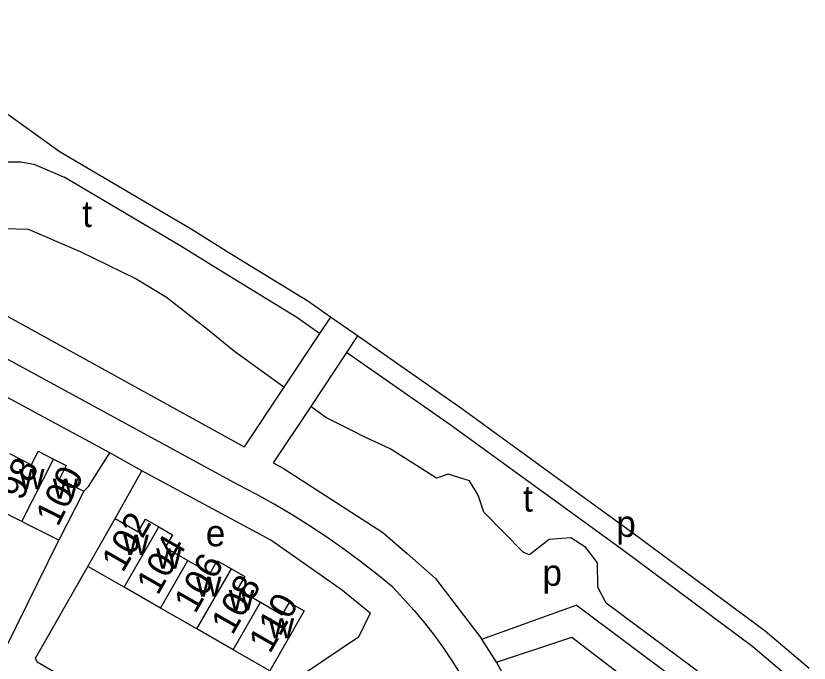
# Model space of a CAD drawing. Extents: x 163012 to 165277, y 382513 to 383987.
# Drawn here: x 164219.5 to 164339.9, y 383557.5 to 383655.8 of the extents above; entities that cross this region are included whole.
import ezdxf

# ---------------------------------------------------------------- set-up
doc = ezdxf.new("R2010")
doc.units = 0
for name, color, linetype in [('BLT_Basislijn', 7, 'Continuous'), ('BLT_Bebouwing', 7, 'Continuous'), ('BLT_Centroide', 7, 'Continuous'), ('BLT_Huisnummer', 7, 'Continuous'), ('BLT_Huisnummer_ tussenligend', 7, 'Continuous'), ('BLT_Onderverdeling_panden', 7, 'Continuous')]:
    doc.layers.add(name, color=color, linetype=linetype)

msp = doc.modelspace()

# ---------------------------------------------------------------- linework, layer by layer
at = {"layer": 'BLT_Basislijn'}
for p, q in [((164253.23, 383584.61), (164174.38, 383627.47)), ((164267.25, 383610.06), (164265.59, 383607.56)), ((164265.59, 383607.56), (164260.18, 383599.42)), ((164271.35, 383607.19), (164269.69, 383604.69)), ((164269.69, 383604.69), (164264.24, 383596.49)), ((164260.18, 383599.42), (164254.16, 383590.37)), ((164264.24, 383596.49), (164258.55, 383587.95)), ((164238.63, 383586.7), (164233.73, 383589.42)), ((164234.57, 383579.46), (164238.63, 383586.7)), ((164292.43, 383557.65), (164290.23, 383561.18))]:
    msp.add_line(p, q, dxfattribs=at)
for points in [[(164260.18, 383599.42), (164252.68, 383604.84), (164248.56, 383608.19), (164242.36, 383613.04), (164237.58, 383615.93), (164229.31, 383619.94), (164221.42, 383623.35), (164217.69, 383623.42), (164211.33, 383622.65), (164207.69, 383623.26), (164204.58, 383624.44), (164202.52, 383625.33), (164199.96, 383627.38), (164196.94, 383630.37), (164195.36, 383632.54), (164193.6, 383635.55), (164192.09, 383638.68), (164189.84, 383644.26), (164189.47, 383645.58), (164189.18, 383647.27), (164189.7, 383651.82), (164189.86, 383654.86), (164189.34, 383655.77)], [(164267.25, 383610.06), (164263.78, 383612.49), (164251.8, 383619.82), (164246.07, 383623.4), (164226.22, 383635.1), (164207.98, 383648.12)], [(164202.53, 383633.42), (164203.91, 383632.72), (164205.4, 383632.16), (164206.96, 383631.77), (164208.58, 383631.56), (164210.22, 383631.54), (164211.84, 383631.7), (164213.41, 383632.05), (164214.91, 383632.57), (164216.32, 383633.23), (164218.17, 383633.61), (164220.24, 383633.61), (164222.21, 383633.24), (164226.8, 383631.28)], [(164179.62, 383631.43), (164254.16, 383590.37)], [(164265.59, 383607.56), (164262.13, 383609.98), (164250.22, 383617.27), (164244.51, 383620.83), (164226.8, 383631.28)], [(164233.73, 383589.42), (164177.23, 383619.95), (164175.65, 383621.7)], [(164271.35, 383607.19), (164267.25, 383610.06)], [(164333.21, 383562.36), (164313.32, 383577.12), (164287.17, 383596.12), (164271.35, 383607.19)], [(164331.34, 383560.01), (164311.54, 383574.7), (164285.42, 383593.67), (164269.69, 383604.69)], [(164270.5, 383592.84), (164266.55, 383594.82), (164264.24, 383596.49)], [(164307.82, 383569.05), (164307.77, 383572.73), (164305.98, 383575.1), (164303.72, 383576.56), (164300.44, 383576.31), (164297.44, 383573.94), (164296.5, 383574.37), (164290.49, 383580.44), (164289.65, 383583.03), (164288.32, 383585.18), (164285.11, 383586.23), (164283.31, 383585.59), (164276.29, 383590.06), (164272.16, 383592), (164270.5, 383592.84)], [(164229.81, 383583.63), (164230.49, 383584.35), (164233.73, 383589.42)], [(164258.55, 383587.95), (164260.22, 383587.03), (164275.17, 383577.33), (164278.87, 383574.18), (164283.2, 383570.39), (164290.23, 383561.18)], [(164273.25, 383565.1), (164269.04, 383568.53), (164258.18, 383576.19), (164238.63, 383586.7)], [(164276.68, 383569.05), (164274.25, 383571.04), (164271.78, 383572.97), (164269.25, 383574.84), (164266.68, 383576.64), (164264.06, 383578.37), (164261.4, 383580.04), (164258.7, 383581.64), (164255.96, 383583.17), (164253.23, 383584.61)], [(164214.7, 383560.28), (164217.72, 383559.52), (164217.96, 383559.84), (164226.03, 383576.17)], [(164273.25, 383565.1), (164271.51, 383561.46), (164246.31, 383544.54), (164245.43, 383544.51), (164222.72, 383557.67), (164222.49, 383558.28), (164230.41, 383572.21)], [(164276.68, 383569.05), (164278.34, 383567.3), (164279.94, 383565.5), (164281.49, 383563.65), (164282.97, 383561.75), (164284.38, 383559.8), (164285.73, 383557.8), (164287.02, 383555.77), (164287.89, 383554.27)], [(164328.84, 383551.9), (164309.09, 383566.65), (164307.82, 383569.05)], [(164290.23, 383561.18), (164304.52, 383566.32)], [(164327.04, 383549.49), (164304.52, 383566.32)], [(164292.43, 383557.65), (164303.85, 383561.46), (164330, 383541.47), (164326.71, 383533), (164326, 383532.84), (164322.97, 383534.1)], [(164339.89, 383556.69), (164333.21, 383562.36)], [(164338.06, 383554.3), (164331.34, 383560.01)], [(164322.97, 383534.1), (164324.03, 383536.46), (164323.74, 383537.24), (164308.89, 383543.6), (164308.12, 383543.46), (164306.07, 383539.27), (164302.69, 383537.71), (164301.8, 383536.73), (164301.43, 383536.7), (164298.02, 383546.8), (164296.56, 383550.22), (164292.43, 383557.65)]]:
    msp.add_lwpolyline(points, dxfattribs=at)
at = {"layer": 'BLT_Bebouwing'}
for p, q in [((164229.81, 383583.63), (164226.03, 383576.17)), ((164220.39, 383579.02), (164214.74, 383581.88)), ((164230.41, 383572.21), (164234.57, 383579.46)), ((164235.93, 383569.04), (164230.41, 383572.21)), ((164241.45, 383565.88), (164235.93, 383569.04)), ((164246.97, 383562.71), (164241.45, 383565.88)), ((164252.49, 383559.55), (164246.97, 383562.71))]:
    msp.add_line(p, q, dxfattribs=at)
for points in [[(164218.51, 383589.32), (164221.84, 383587.64), (164222.87, 383589.68), (164225.19, 383588.5)], [(164225.19, 383588.5), (164227.14, 383587.52), (164226.12, 383585.5), (164229.81, 383583.63)], [(164234.57, 383579.46), (164238.05, 383577.46), (164239.16, 383579.39), (164241.19, 383578.22)], [(164226.03, 383576.17), (164221.57, 383578.42), (164220.39, 383579.02)], [(164241.19, 383578.22), (164243.28, 383577.02), (164242.16, 383575.07), (164245.6, 383573.1)], [(164245.6, 383573.1), (164248.96, 383571.17), (164250.04, 383573.06), (164252.2, 383571.82)], [(164252.2, 383571.82), (164254.22, 383570.67), (164253.13, 383568.78), (164256.64, 383566.77)], [(164256.64, 383566.77), (164259.93, 383564.88), (164261, 383566.74), (164263.23, 383565.47), (164258.01, 383556.38), (164252.49, 383559.55)]]:
    msp.add_lwpolyline(points, dxfattribs=at)
at = {"layer": 'BLT_Onderverdeling_panden'}
for p, q in [((164220.39, 383579.02), (164225.19, 383588.5)), ((164235.93, 383569.04), (164241.19, 383578.22)), ((164241.45, 383565.88), (164245.6, 383573.1)), ((164246.97, 383562.71), (164252.2, 383571.82)), ((164252.49, 383559.55), (164256.64, 383566.77))]:
    msp.add_line(p, q, dxfattribs=at)

# ---------------------------------------------------------------- texts
at = {"layer": 'BLT_Centroide'}
for s, p in [('t', (164229.57, 383623.72)), ('w', (164219.97, 383583.92)), ('w', (164225.09, 383582.47)), ('t', (164296.46, 383580.52)), ('p', (164310.6, 383576.69)), ('e', (164248.31, 383575.26)), ('w', (164235.8, 383573.94)), ('w', (164240.77, 383571.88)), ('p', (164299.4, 383569.26)), ('w', (164246.83, 383567.59)), ('w', (164251.81, 383565.53)), ('w', (164257.86, 383561.27))]:
    msp.add_text(s, height=4, dxfattribs=at).set_placement(p)
at = {"layer": 'BLT_Huisnummer'}
for s, rotation, p in [('100', 63.1501, (164225.86, 383578.1)), ('102', 60.1655, (164235.72, 383571.12)), ('106', 60.1645, (164246.71, 383564.89)), ('110', 60.1608, (164258.05, 383558.84))]:
    msp.add_text(s, height=4, rotation=rotation, dxfattribs=at).set_placement(p)
at = {"layer": 'BLT_Huisnummer_ tussenligend'}
for s, rotation, p in [('98', 63.1523, (164220.39, 383582.04)), ('104', 60.1655, (164241.02, 383567.68)), ('108', 60.1645, (164252.36, 383561.64))]:
    msp.add_text(s, height=4, rotation=rotation, dxfattribs=at).set_placement(p)

doc.saveas('drawing.dxf')
